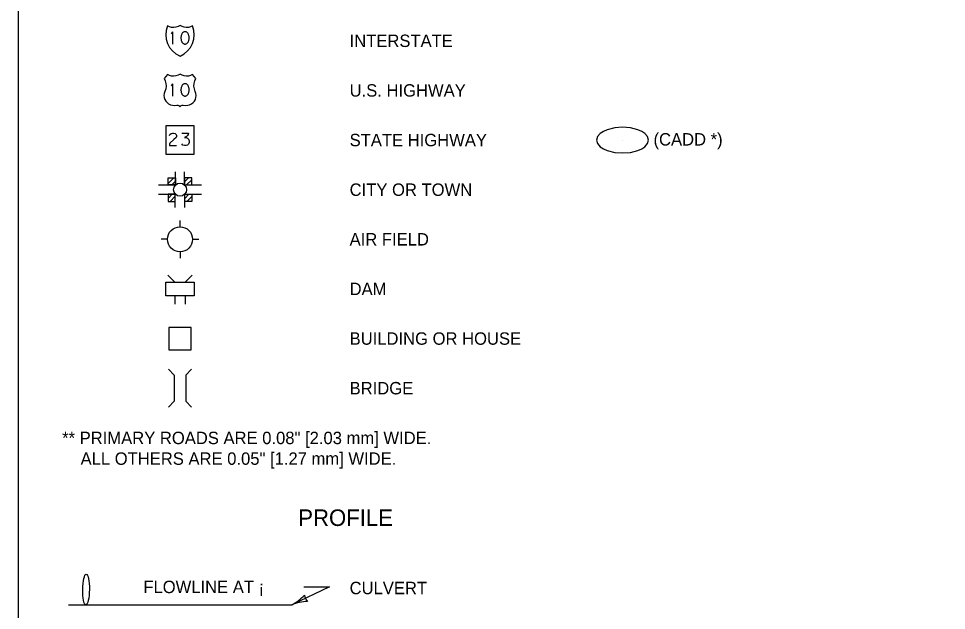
# Model space of a CAD drawing. Extents: x 49991.4 to 50021, y 49987.6 to 50011.4.
# Drawn here: x 49999.384 to 50003.87, y 49990.62 to 49993.483 of the extents above; entities that cross this region are included whole.
import ezdxf

# ---------------------------------------------------------------- set-up
doc = ezdxf.new("R2010")
doc.units = 0
for name, color, linetype in [('Level 1', 7, 'Continuous'), ('Level 2', 7, 'Continuous'), ('Level 3', 7, 'Continuous')]:
    doc.layers.add(name, color=color, linetype=linetype)

msp = doc.modelspace()

# ---------------------------------------------------------------- linework, layer by layer
at = {"layer": 'Level 1'}
for p, q in [((50000.1643, 49993.4489), (50000.1548, 49993.4439)), ((50000.1739, 49993.4439), (50000.1643, 49993.4489)), ((50000.1134, 49993.4426), (50000.1038, 49993.447)), ((50000.1237, 49993.4401), (50000.1134, 49993.4426)), ((50000.1278, 49993.4192), (50000.1219, 49993.4089)), ((50000.1343, 49993.4395), (50000.1237, 49993.4401)), ((50000.1278, 49993.4192), (50000.1278, 49993.3592)), ((50000.1447, 49993.4407), (50000.1343, 49993.4395)), ((50000.1548, 49993.4439), (50000.1447, 49993.4407)), ((50000.1713, 49993.4042), (50000.1703, 49993.4014)), ((50000.1724, 49993.4069), (50000.1713, 49993.4042)), ((50000.1737, 49993.4093), (50000.1724, 49993.4069)), ((50000.1752, 49993.4115), (50000.1737, 49993.4093)), ((50000.1839, 49993.4407), (50000.1739, 49993.4439)), ((50000.1768, 49993.4135), (50000.1752, 49993.4115)), ((50000.1786, 49993.4152), (50000.1768, 49993.4135)), ((50000.1804, 49993.4166), (50000.1786, 49993.4152)), ((50000.1823, 49993.4178), (50000.1804, 49993.4166)), ((50000.1844, 49993.4186), (50000.1823, 49993.4178)), ((50000.1944, 49993.4395), (50000.1839, 49993.4407)), ((50000.1864, 49993.4191), (50000.1844, 49993.4186)), ((50000.1885, 49993.4192), (50000.1864, 49993.4191)), ((50000.1905, 49993.4191), (50000.1885, 49993.4192)), ((50000.1926, 49993.4186), (50000.1905, 49993.4191)), ((50000.1946, 49993.4178), (50000.1926, 49993.4186)), ((50000.205, 49993.4401), (50000.1944, 49993.4395)), ((50000.1965, 49993.4166), (50000.1946, 49993.4178)), ((50000.1984, 49993.4152), (50000.1965, 49993.4166)), ((50000.2001, 49993.4135), (50000.1984, 49993.4152)), ((50000.2018, 49993.4115), (50000.2001, 49993.4135)), ((50000.2032, 49993.4093), (50000.2018, 49993.4115)), ((50000.2045, 49993.4069), (50000.2032, 49993.4093)), ((50000.2057, 49993.4042), (50000.2045, 49993.4069)), ((50000.2152, 49993.4426), (50000.205, 49993.4401)), ((50000.2066, 49993.4015), (50000.2057, 49993.4042)), ((50000.2249, 49993.447), (50000.2152, 49993.4426)), ((50000.1687, 49993.3924), (50000.1686, 49993.3892)), ((50000.1686, 49993.3892), (50000.1687, 49993.3861)), ((50000.1691, 49993.3955), (50000.1687, 49993.3924)), ((50000.1687, 49993.3861), (50000.1691, 49993.383)), ((50000.1696, 49993.3985), (50000.1691, 49993.3955)), ((50000.1691, 49993.383), (50000.1696, 49993.38)), ((50000.1703, 49993.4014), (50000.1696, 49993.3985)), ((50000.1696, 49993.38), (50000.1703, 49993.377)), ((50000.1703, 49993.377), (50000.1713, 49993.3742)), ((50000.1713, 49993.3742), (50000.1724, 49993.3716)), ((50000.1724, 49993.3716), (50000.1737, 49993.3692)), ((50000.1737, 49993.3692), (50000.1752, 49993.367)), ((50000.1752, 49993.367), (50000.1768, 49993.365)), ((50000.1768, 49993.365), (50000.1786, 49993.3633)), ((50000.1786, 49993.3633), (50000.1804, 49993.3618)), ((50000.1804, 49993.3618), (50000.1823, 49993.3607)), ((50000.1823, 49993.3607), (50000.1844, 49993.3599)), ((50000.1844, 49993.3599), (50000.1864, 49993.3594)), ((50000.1864, 49993.3594), (50000.1885, 49993.3592)), ((50000.1885, 49993.3592), (50000.1905, 49993.3594)), ((50000.1905, 49993.3594), (50000.1926, 49993.3599)), ((50000.1926, 49993.3599), (50000.1946, 49993.3607)), ((50000.1946, 49993.3607), (50000.1965, 49993.3618)), ((50000.1965, 49993.3618), (50000.1984, 49993.3633)), ((50000.1984, 49993.3633), (50000.2001, 49993.365)), ((50000.2001, 49993.365), (50000.2018, 49993.367)), ((50000.2018, 49993.367), (50000.2032, 49993.3692)), ((50000.2032, 49993.3692), (50000.2045, 49993.3716)), ((50000.2045, 49993.3716), (50000.2057, 49993.3742)), ((50000.2057, 49993.3742), (50000.2066, 49993.377)), ((50000.2073, 49993.3985), (50000.2066, 49993.4015)), ((50000.2066, 49993.377), (50000.2073, 49993.38)), ((50000.2079, 49993.3955), (50000.2073, 49993.3985)), ((50000.2073, 49993.38), (50000.2079, 49993.383)), ((50000.2082, 49993.3924), (50000.2079, 49993.3955)), ((50000.2079, 49993.383), (50000.2082, 49993.3861)), ((50000.2083, 49993.3892), (50000.2082, 49993.3924)), ((50000.2082, 49993.3861), (50000.2083, 49993.3892)), ((50000.1038, 49993.2118), (50000.0876, 49993.1932)), ((50000.0876, 49993.1932), (50000.0931, 49993.1813)), ((50000.0931, 49993.1813), (50000.0962, 49993.1686)), ((50000.1134, 49993.2074), (50000.1038, 49993.2118)), ((50000.1237, 49993.2049), (50000.1134, 49993.2074)), ((50000.1343, 49993.2043), (50000.1237, 49993.2049)), ((50000.1447, 49993.2055), (50000.1343, 49993.2043)), ((50000.1548, 49993.2087), (50000.1447, 49993.2055)), ((50000.1643, 49993.2137), (50000.1548, 49993.2087)), ((50000.1739, 49993.2087), (50000.1643, 49993.2137)), ((50000.1839, 49993.2055), (50000.1739, 49993.2087)), ((50000.1944, 49993.2043), (50000.1839, 49993.2055)), ((50000.205, 49993.2049), (50000.1944, 49993.2043)), ((50000.2152, 49993.2074), (50000.205, 49993.2049)), ((50000.2249, 49993.2118), (50000.2152, 49993.2074)), ((50000.2411, 49993.1932), (50000.2249, 49993.2118)), ((50000.2324, 49993.1686), (50000.2356, 49993.1813)), ((50000.2356, 49993.1813), (50000.2411, 49993.1932)), ((50000.0951, 49993.1426), (50000.0909, 49993.1303)), ((50000.097, 49993.1556), (50000.0951, 49993.1426)), ((50000.0962, 49993.1686), (50000.097, 49993.1556)), ((50000.1278, 49993.1677), (50000.1219, 49993.1574)), ((50000.1278, 49993.1677), (50000.1278, 49993.1077)), ((50000.1643, 49993.1352), (50000.1643, 49993.1352)), ((50000.1687, 49993.1409), (50000.1686, 49993.1377)), ((50000.1686, 49993.1377), (50000.1687, 49993.1346)), ((50000.1691, 49993.144), (50000.1687, 49993.1409)), ((50000.1687, 49993.1346), (50000.1691, 49993.1315)), ((50000.1696, 49993.147), (50000.1691, 49993.144)), ((50000.1703, 49993.1499), (50000.1696, 49993.147)), ((50000.1713, 49993.1527), (50000.1703, 49993.1499)), ((50000.1724, 49993.1554), (50000.1713, 49993.1527)), ((50000.1737, 49993.1578), (50000.1724, 49993.1554)), ((50000.1752, 49993.16), (50000.1737, 49993.1578)), ((50000.1768, 49993.162), (50000.1752, 49993.16)), ((50000.1786, 49993.1637), (50000.1768, 49993.162)), ((50000.1804, 49993.1651), (50000.1786, 49993.1637)), ((50000.1823, 49993.1663), (50000.1804, 49993.1651)), ((50000.1844, 49993.1671), (50000.1823, 49993.1663)), ((50000.1864, 49993.1676), (50000.1844, 49993.1671)), ((50000.1885, 49993.1677), (50000.1864, 49993.1676)), ((50000.1905, 49993.1676), (50000.1885, 49993.1677)), ((50000.1926, 49993.1671), (50000.1905, 49993.1676)), ((50000.1946, 49993.1663), (50000.1926, 49993.1671)), ((50000.1965, 49993.1651), (50000.1946, 49993.1663)), ((50000.1984, 49993.1637), (50000.1965, 49993.1651)), ((50000.2001, 49993.162), (50000.1984, 49993.1637)), ((50000.2018, 49993.16), (50000.2001, 49993.162)), ((50000.2032, 49993.1578), (50000.2018, 49993.16)), ((50000.2045, 49993.1554), (50000.2032, 49993.1578)), ((50000.2057, 49993.1527), (50000.2045, 49993.1554)), ((50000.2066, 49993.15), (50000.2057, 49993.1527)), ((50000.2073, 49993.147), (50000.2066, 49993.15)), ((50000.2079, 49993.144), (50000.2073, 49993.147)), ((50000.2082, 49993.1409), (50000.2079, 49993.144)), ((50000.2079, 49993.1315), (50000.2082, 49993.1346)), ((50000.2083, 49993.1377), (50000.2082, 49993.1409)), ((50000.2082, 49993.1346), (50000.2083, 49993.1377)), ((50000.2317, 49993.1556), (50000.2324, 49993.1686)), ((50000.2335, 49993.1426), (50000.2317, 49993.1556)), ((50000.2377, 49993.1303), (50000.2335, 49993.1426)), ((50000.0878, 49993.121), (50000.0867, 49993.1113)), ((50000.0867, 49993.1113), (50000.0875, 49993.1015)), ((50000.0875, 49993.1015), (50000.0904, 49993.0921)), ((50000.0909, 49993.1303), (50000.0878, 49993.121)), ((50000.0904, 49993.0921), (50000.095, 49993.0835)), ((50000.1691, 49993.1315), (50000.1696, 49993.1285)), ((50000.1696, 49993.1285), (50000.1703, 49993.1255)), ((50000.1703, 49993.1255), (50000.1713, 49993.1227)), ((50000.1713, 49993.1227), (50000.1724, 49993.1201)), ((50000.1724, 49993.1201), (50000.1737, 49993.1177)), ((50000.1737, 49993.1177), (50000.1752, 49993.1155)), ((50000.1752, 49993.1155), (50000.1768, 49993.1135)), ((50000.1768, 49993.1135), (50000.1786, 49993.1118)), ((50000.1786, 49993.1118), (50000.1804, 49993.1103)), ((50000.1804, 49993.1103), (50000.1823, 49993.1092)), ((50000.1823, 49993.1092), (50000.1844, 49993.1084)), ((50000.1844, 49993.1084), (50000.1864, 49993.1079)), ((50000.1864, 49993.1079), (50000.1885, 49993.1077)), ((50000.1885, 49993.1077), (50000.1905, 49993.1079)), ((50000.1905, 49993.1079), (50000.1926, 49993.1084)), ((50000.1926, 49993.1084), (50000.1946, 49993.1092)), ((50000.1946, 49993.1092), (50000.1965, 49993.1103)), ((50000.1965, 49993.1103), (50000.1984, 49993.1118)), ((50000.1984, 49993.1118), (50000.2001, 49993.1135)), ((50000.2001, 49993.1135), (50000.2018, 49993.1155)), ((50000.2018, 49993.1155), (50000.2032, 49993.1177)), ((50000.2032, 49993.1177), (50000.2045, 49993.1201)), ((50000.2045, 49993.1201), (50000.2057, 49993.1227)), ((50000.2057, 49993.1227), (50000.2066, 49993.1255)), ((50000.2066, 49993.1255), (50000.2073, 49993.1285)), ((50000.2073, 49993.1285), (50000.2079, 49993.1315)), ((50000.2336, 49993.0835), (50000.2383, 49993.0921)), ((50000.2408, 49993.121), (50000.2377, 49993.1303)), ((50000.2383, 49993.0921), (50000.2411, 49993.1015)), ((50000.242, 49993.1113), (50000.2408, 49993.121)), ((50000.2411, 49993.1015), (50000.242, 49993.1113)), ((50000.095, 49993.0835), (50000.1013, 49993.076)), ((50000.1013, 49993.076), (50000.109, 49993.0699)), ((50000.109, 49993.0699), (50000.1178, 49993.0656)), ((50000.1178, 49993.0656), (50000.1272, 49993.0631)), ((50000.1272, 49993.0631), (50000.137, 49993.0625)), ((50000.137, 49993.0625), (50000.1493, 49993.0643)), ((50000.1493, 49993.0643), (50000.1543, 49993.064)), ((50000.1543, 49993.064), (50000.159, 49993.062)), ((50000.159, 49993.062), (50000.1628, 49993.0586)), ((50000.1628, 49993.0586), (50000.1643, 49993.0566)), ((50000.1643, 49993.0566), (50000.1658, 49993.0586)), ((50000.1658, 49993.0586), (50000.1696, 49993.062)), ((50000.1696, 49993.062), (50000.1743, 49993.064)), ((50000.1743, 49993.064), (50000.1793, 49993.0643)), ((50000.1793, 49993.0643), (50000.1916, 49993.0625)), ((50000.1916, 49993.0625), (50000.2014, 49993.0631)), ((50000.2014, 49993.0631), (50000.2108, 49993.0656)), ((50000.2108, 49993.0656), (50000.2196, 49993.0699)), ((50000.2196, 49993.0699), (50000.2273, 49993.076)), ((50000.2273, 49993.076), (50000.2336, 49993.0835)), ((50000.2333, 49992.9642), (50000.0953, 49992.9642)), ((50000.0953, 49992.9642), (50000.0953, 49992.8262)), ((50000.2333, 49992.8262), (50000.2333, 49992.9642)), ((50002.3039, 49992.9576), (50002.2662, 49992.9547)), ((50002.3417, 49992.9547), (50002.3039, 49992.9576)), ((50000.1138, 49992.917), (50000.1157, 49992.9226)), ((50000.1157, 49992.9226), (50000.1209, 49992.9274)), ((50000.1209, 49992.9274), (50000.128, 49992.9292)), ((50000.128, 49992.9292), (50000.1332, 49992.9292)), ((50000.1332, 49992.9292), (50000.1403, 49992.9274)), ((50000.1403, 49992.9274), (50000.1455, 49992.9222)), ((50000.1455, 49992.9222), (50000.1478, 49992.917)), ((50000.1478, 49992.9118), (50000.1459, 49992.9075)), ((50000.1478, 49992.917), (50000.1478, 49992.9118)), ((50000.1738, 49992.9292), (50000.2055, 49992.9292)), ((50000.1955, 49992.9122), (50000.1861, 49992.9075)), ((50000.2003, 49992.917), (50000.1955, 49992.9122)), ((50000.2036, 49992.9222), (50000.2003, 49992.917)), ((50000.2055, 49992.9292), (50000.2036, 49992.9222)), ((50002.1832, 49992.9118), (50002.1787, 49992.8952)), ((50002.1965, 49992.9273), (50002.1832, 49992.9118)), ((50002.2112, 49992.9371), (50002.1965, 49992.9273)), ((50002.2295, 49992.9454), (50002.2112, 49992.9371)), ((50002.2662, 49992.9547), (50002.2295, 49992.9454)), ((50002.3783, 49992.9454), (50002.3417, 49992.9547)), ((50002.3967, 49992.9371), (50002.3783, 49992.9454)), ((50002.4113, 49992.9273), (50002.3967, 49992.9371)), ((50002.4246, 49992.9118), (50002.4113, 49992.9273)), ((50002.4292, 49992.8952), (50002.4246, 49992.9118)), ((50000.1157, 49992.8796), (50000.1138, 49992.8749)), ((50000.1138, 49992.8749), (50000.1138, 49992.8692)), ((50000.1138, 49992.8692), (50000.1478, 49992.8692)), ((50000.1341, 49992.8985), (50000.1157, 49992.8796)), ((50000.1459, 49992.9075), (50000.1341, 49992.8985)), ((50000.1781, 49992.8711), (50000.1738, 49992.8763)), ((50000.1851, 49992.8692), (50000.1781, 49992.8711)), ((50000.1932, 49992.8692), (50000.1851, 49992.8692)), ((50000.1861, 49992.9075), (50000.1932, 49992.9075)), ((50000.1932, 49992.9075), (50000.2007, 49992.9042)), ((50000.2003, 49992.8711), (50000.1932, 49992.8692)), ((50000.2055, 49992.8759), (50000.2003, 49992.8711)), ((50000.2007, 49992.9042), (50000.2055, 49992.8995)), ((50000.2055, 49992.8995), (50000.2078, 49992.8919)), ((50000.2078, 49992.8839), (50000.2055, 49992.8759)), ((50000.2078, 49992.8919), (50000.2078, 49992.8839)), ((50002.1787, 49992.8952), (50002.1832, 49992.8785)), ((50002.1832, 49992.8785), (50002.1965, 49992.8631)), ((50002.3039, 49992.8952), (50002.3039, 49992.8952)), ((50002.4113, 49992.8631), (50002.4246, 49992.8785)), ((50002.4246, 49992.8785), (50002.4292, 49992.8952)), ((50000.0953, 49992.8262), (50000.2333, 49992.8262)), ((50002.1965, 49992.8631), (50002.2112, 49992.8532)), ((50002.2112, 49992.8532), (50002.2295, 49992.845)), ((50002.2295, 49992.845), (50002.2662, 49992.8356)), ((50002.2662, 49992.8356), (50002.3039, 49992.8327)), ((50002.3039, 49992.8327), (50002.3417, 49992.8356)), ((50002.3417, 49992.8356), (50002.3783, 49992.845)), ((50002.3783, 49992.845), (50002.3967, 49992.8532)), ((50002.3967, 49992.8532), (50002.4113, 49992.8631)), ((50000.1423, 49992.6782), (50000.1423, 49992.7416)), ((50000.1862, 49992.6782), (50000.1862, 49992.7416)), ((50000.1077, 49992.71), (50000.1104, 49992.7127)), ((50000.1077, 49992.6856), (50000.1349, 49992.7127)), ((50000.1077, 49992.6782), (50000.1077, 49992.7127)), ((50000.1077, 49992.7127), (50000.1423, 49992.7127)), ((50000.1247, 49992.6782), (50000.1423, 49992.6957)), ((50000.1423, 49992.7127), (50000.1423, 49992.6782)), ((50000.1862, 49992.6933), (50000.2057, 49992.7127)), ((50000.2208, 49992.7127), (50000.1862, 49992.7127)), ((50000.1862, 49992.7127), (50000.1862, 49992.6782)), ((50000.1956, 49992.6782), (50000.2208, 49992.7035)), ((50000.2208, 49992.6782), (50000.2208, 49992.7127)), ((50000.0606, 49992.6782), (50000.1423, 49992.6782)), ((50000.1423, 49992.6782), (50000.1077, 49992.6782)), ((50000.1862, 49992.6782), (50000.268, 49992.6782)), ((50000.1862, 49992.6782), (50000.2208, 49992.6782)), ((50000.22, 49992.6782), (50000.2208, 49992.679)), ((50000.0606, 49992.633), (50000.1414, 49992.633)), ((50000.1068, 49992.6131), (50000.1268, 49992.633)), ((50000.1414, 49992.633), (50000.1068, 49992.633)), ((50000.1068, 49992.633), (50000.1068, 49992.5985)), ((50000.1068, 49992.5985), (50000.1414, 49992.5985)), ((50000.1166, 49992.5985), (50000.1414, 49992.6232)), ((50000.1411, 49992.5985), (50000.1414, 49992.5988)), ((50000.1414, 49992.5688), (50000.1414, 49992.633)), ((50000.1414, 49992.5985), (50000.1414, 49992.633)), ((50000.1871, 49992.5688), (50000.1871, 49992.633)), ((50000.1871, 49992.633), (50000.268, 49992.633)), ((50000.1871, 49992.6126), (50000.2076, 49992.633)), ((50000.1871, 49992.633), (50000.2217, 49992.633)), ((50000.1871, 49992.5985), (50000.1871, 49992.633)), ((50000.2217, 49992.5985), (50000.1871, 49992.5985)), ((50000.1974, 49992.5985), (50000.2217, 49992.6227)), ((50000.2217, 49992.633), (50000.2217, 49992.5985)), ((50000.1643, 49992.4757), (50000.1643, 49992.5057)), ((50000.1037, 49992.4152), (50000.0737, 49992.4152)), ((50000.2249, 49992.4152), (50000.2549, 49992.4152)), ((50000.1643, 49992.3546), (50000.1643, 49992.3246)), ((50000.1397, 49992.2079), (50000.1058, 49992.2418)), ((50000.189, 49992.2079), (50000.2229, 49992.2418)), ((50000.096, 49992.2079), (50000.2327, 49992.2079)), ((50000.096, 49992.1425), (50000.096, 49992.2079)), ((50000.2327, 49992.2079), (50000.2327, 49992.1425)), ((50000.2327, 49992.1425), (50000.096, 49992.1425)), ((50000.1397, 49992.1425), (50000.1397, 49992.1016)), ((50000.189, 49992.1425), (50000.189, 49992.1016)), ((50000.2183, 49991.9892), (50000.1103, 49991.9892)), ((50000.1103, 49991.9892), (50000.1103, 49991.8812)), ((50000.2183, 49991.8812), (50000.2183, 49991.9892)), ((50000.1103, 49991.8812), (50000.2183, 49991.8812)), ((50000.1366, 49991.7586), (50000.1081, 49991.7871)), ((50000.1366, 49991.7586), (50000.1366, 49991.6319)), ((50000.192, 49991.7586), (50000.2205, 49991.7871)), ((50000.192, 49991.7586), (50000.192, 49991.6319)), ((50000.1081, 49991.6034), (50000.1366, 49991.6319)), ((50000.2205, 49991.6034), (50000.192, 49991.6319)), ((49999.6243, 49990.6467), (50000.7043, 49990.6467))]:
    msp.add_line(p, q, dxfattribs=at)
msp.add_lwpolyline([(49999.3835, 49998.9992), (50016.7501, 49998.9992), (50016.7501, 49987.7988), (49999.3835, 49987.7988)], close=True, dxfattribs=at)
for centre, radius in [((50000.1643, 49992.6552), 0.0316), ((50000.1643, 49992.4152), 0.0606)]:
    msp.add_circle(centre, radius, dxfattribs=at)
for centre, major_axis, start_param, end_param in [((50000.207, 49993.4041), (0.1032, -0.043), 3.141593, 4.712389), ((50000.1216, 49993.4041), (0.1032, 0.043), 4.712389, 6.283185)]:
    msp.add_ellipse(centre, major_axis=major_axis, ratio=0.99438, start_param=start_param, end_param=end_param, dxfattribs=at)
msp.add_ellipse((49999.7098, 49990.7216), major_axis=(-0.0011, -0.0743), ratio=0.219239, dxfattribs=at)
at = {"layer": 'Level 3'}
for p, q in [((50000.8877, 49990.7341), (50000.7043, 49990.6467)), ((50000.7633, 49990.7341), (50000.8877, 49990.7341))]:
    msp.add_line(p, q, dxfattribs=at)
for centre, radius, start, end in [((50000.5938, 49990.8519), 0.233, 298.3072, 317.557), ((50000.82, 49990.7019), 0.0548, 187.6187, 223.341), ((50000.7916, 49990.4423), 0.2223, 92.9359, 113.1194)]:
    msp.add_arc(centre, radius, start, end, dxfattribs=at)

# ---------------------------------------------------------------- texts
at = {"layer": 'Level 2'}
for s, height, p in [('INTERSTATE          ', 0.059999, (50000.9843, 49993.3452)), ('U.S. HIGHWAY        ', 0.059999, (50000.9843, 49993.1052)), ('STATE HIGHWAY       ', 0.059999, (50000.9843, 49992.8652)), ('(CADD *)', 0.06, (50002.4537, 49992.8687)), ('CITY OR TOWN        ', 0.059999, (50000.9843, 49992.6252)), ('AIR FIELD           ', 0.059999, (50000.9843, 49992.3852)), ('DAM                 ', 0.059999, (50000.9843, 49992.1452)), ('BUILDING OR HOUSE   ', 0.059999, (50000.9843, 49991.9052)), ('BRIDGE              ', 0.059999, (50000.9843, 49991.6652)), ('** PRIMARY ROADS ARE 0.08" [2.03 mm] WIDE.', 0.06, (49999.5943, 49991.4246)), ('    ALL OTHERS ARE 0.05" [1.27 mm] WIDE.', 0.06, (49999.5943, 49991.3246)), ('PROFILE', 0.08, (50000.7361, 49991.0288)), ('FLOWLINE AT ¡', 0.06, (49999.987, 49990.7041)), ('CULVERT             ', 0.059999, (50000.9843, 49990.6988))]:
    msp.add_text(s, height=height, dxfattribs=at).set_placement(p)

doc.saveas('drawing.dxf')
